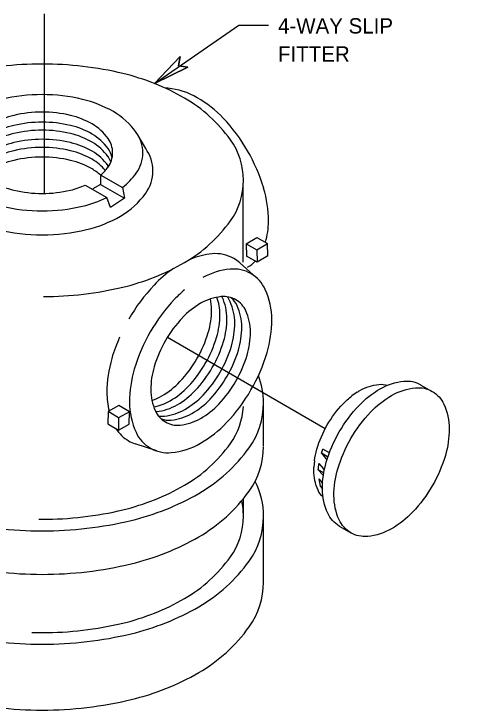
# Model space of a CAD drawing. Extents: x -224.9 to -217.6, y 224 to 234.
# Drawn here: x -223.209 to -221.41, y 227.932 to 230.657 of the extents above; entities that cross this region are included whole.
import ezdxf

# ---------------------------------------------------------------- set-up
doc = ezdxf.new("R2010")
doc.units = 0
for name, color, linetype in [('Default', 7, 'Continuous'), ('DETL-DIMS', 7, 'Continuous'), ('DETL-LINE', 7, 'Continuous'), ('DETL-NOTE', 7, 'Continuous')]:
    doc.layers.add(name, color=color, linetype=linetype)

# ---------------------------------------------------------------- blocks, each defined once
blk = doc.blocks.new('DWG009')
at = {"layer": 'Default'}
for p, q in [((-1.0426, -0.1786), (-1.0426, -0.0086)), ((1.0555, -0.1752), (1.0555, -0.0085)), ((-0.7214, -0.6491), (-0.7364, -0.6066)), ((-0.7214, -0.6151), (-0.7214, -0.6491)), ((-0.6471, -0.7137), (-0.7214, -0.6491)), ((-0.6471, -0.7137), (-0.6729, -0.6408)), ((-0.5779, -0.6986), (-0.5793, -0.6827)), ((-0.5502, -0.7768), (-0.5779, -0.6986)), ((-0.5502, -0.6939), (-0.5502, -0.7768)), ((-0.5037, -0.7299), (-0.5058, -0.7069)), ((-0.476, -0.8081), (-0.5037, -0.7299)), ((-0.375, -0.7689), (-0.3771, -0.7459)), ((-0.3473, -0.8471), (-0.375, -0.7689)), ((-0.3473, -0.7536), (-0.3473, -0.8471)), ((-0.2916, -0.7598), (-0.2916, -0.8591)), ((-0.476, -0.8763), (-0.5502, -0.8416)), ((0.5634, -0.8416), (0.4891, -0.8763))]:
    blk.add_line(p, q, dxfattribs=at)
for centre, radius, start, end in [((-0.1359, -0.6173), 1.1998, 103.44948, 120), ((0.0066, -1.2132), 1.8125, 90, 103.44948), ((0.0066, -1.2132), 1.8125, 76.55052, 90), ((0.1491, -0.6173), 1.1998, 60, 76.55052), ((-0.3528, -0.2417), 0.7661, 120, 144.34287), ((0.366, -0.2417), 0.7661, 35.65713, 60), ((-0.6801, -0.0069), 0.3633, 144.34287, 180), ((0.6932, -0.0069), 0.3633, 0, 35.65713), ((-0.6801, -0.0069), 0.3633, 180, 215.65713), ((0.6932, -0.0069), 0.3633, 324.34287, 360), ((-0.6801, -0.1783), 0.3633, 180, 215.65713), ((0.6932, -0.1783), 0.3633, 324.34287, 0), ((-0.3528, 0.2279), 0.7661, 215.65713, 240), ((0.366, 0.2279), 0.7661, 300, 324.34287), ((-0.3528, 0.0565), 0.7661, 215.65713, 240), ((-0.1359, 0.6035), 1.1998, 240, 256.55052), ((0.1491, 0.6035), 1.1998, 283.44948, 300), ((0.366, 0.0565), 0.7661, 300, 324.34287), ((-0.5427, -0.4784), 0.2906, 193.56979, 215.65713), ((-0.1359, 0.4321), 1.1998, 240, 256.55052), ((0.0066, 1.1995), 1.8125, 256.55052, 270), ((0.0066, 1.1995), 1.8125, 270, 283.44948), ((0.1491, 0.4321), 1.1998, 283.44948, 300), ((0.5559, -0.4784), 0.2906, 324.34287, 346.43021), ((-0.2809, -0.2905), 0.6128, 215.65713, 240), ((0.2941, -0.2905), 0.6128, 300, 324.34287), ((-0.115, 0.1519), 1.0256, 244.88835, 249.39036), ((0.0066, 1.028), 1.8125, 256.55052, 270), ((0.0066, 1.028), 1.8125, 270, 283.44948), ((-0.1074, 0.01), 0.9598, 240, 242.52731), ((-0.1074, 0.01), 0.9598, 247.41975, 256.55052), ((-0.1548, 0.0435), 0.9112, 257.80215, 261.45991), ((0.1206, 0.01), 0.9598, 283.44948, 292.58025), ((0.1206, 0.01), 0.9598, 297.47269, 300), ((0.0066, 0.4867), 1.45, 256.55052, 270), ((0.0066, 0.4867), 1.45, 270, 283.44948)]:
    blk.add_arc(centre, radius, start, end, dxfattribs=at)

msp = doc.modelspace()

# ---------------------------------------------------------------- linework, layer by layer
at = {"layer": 'DETL-DIMS'}
for p, q in [((-223.0898, 230.657), (-223.0898, 229.9543)), ((-222.6574, 230.3843), (-222.3274, 230.6133)), ((-222.3274, 230.6133), (-222.2118, 230.6133)), ((-222.6574, 230.3843), (-222.5575, 230.4897)), ((-222.5641, 230.4534), (-222.5575, 230.4897)), ((-222.6574, 230.3843), (-222.5274, 230.4491)), ((-222.5274, 230.4491), (-222.5641, 230.4534)), ((-222.6074, 229.3916), (-221.9886, 229.0343))]:
    msp.add_line(p, q, dxfattribs=at)
msp.add_lwpolyline([(-222.5274, 230.4491), (-222.6574, 230.3843), (-222.5575, 230.4897), (-222.5641, 230.4534)], close=True, dxfattribs=at)
at = {"layer": 'DETL-LINE'}
for p, q in [((-222.6924, 230.1301), (-222.7217, 230.1813)), ((-222.6924, 230.1301), (-222.6924, 230.1301)), ((-222.8688, 230.0256), (-222.8694, 229.9891)), ((-222.8679, 230.0264), (-222.7829, 229.9774)), ((-222.929, 229.9873), (-222.8449, 229.9388)), ((-222.8694, 229.9891), (-222.9, 229.9718)), ((-222.8694, 229.9891), (-222.7785, 229.9369)), ((-222.31, 229.6854), (-222.31, 229.9842)), ((-222.7829, 229.9774), (-222.7748, 229.9361)), ((-222.8305, 229.899), (-222.8449, 229.9388)), ((-222.7748, 229.9361), (-222.8305, 229.899)), ((-222.2982, 229.7578), (-222.2565, 229.7821)), ((-222.2565, 229.7821), (-222.2146, 229.7582)), ((-222.2982, 229.7578), (-222.2563, 229.7339)), ((-222.2982, 229.7578), (-222.298, 229.7095)), ((-222.2563, 229.7339), (-222.2146, 229.7582)), ((-222.2144, 229.7099), (-222.2146, 229.7582)), ((-222.256, 229.6856), (-222.298, 229.7095)), ((-222.2563, 229.7339), (-222.256, 229.6856)), ((-222.2144, 229.7099), (-222.256, 229.6856)), ((-222.2578, 229.6245), (-222.324, 229.6831)), ((-222.798, 229.1243), (-222.8399, 229.1004)), ((-222.7563, 229.1), (-222.798, 229.1243)), ((-222.2306, 228.9671), (-222.2306, 229.1343)), ((-222.8399, 229.1004), (-222.8402, 229.0521)), ((-222.7983, 229.076), (-222.8399, 229.1004)), ((-222.7563, 229.1), (-222.7983, 229.076)), ((-222.7566, 229.0517), (-222.7563, 229.1)), ((-222.7983, 229.076), (-222.7985, 229.0277)), ((-222.8402, 229.0521), (-222.7985, 229.0277)), ((-222.7985, 229.0277), (-222.7566, 229.0517)), ((-222.6493, 228.9464), (-222.7332, 228.9745)), ((-222.3094, 228.7012), (-222.3094, 228.759)), ((-222.2306, 228.4332), (-222.2306, 228.6907))]:
    msp.add_line(p, q, dxfattribs=at)
for centre, radius, start, end in [((-223.0979, 229.0997), 1.3612, 90, 103.4495), ((-223.0979, 229.0997), 1.3612, 76.5505, 90), ((-222.9909, 229.5473), 0.901, 60, 76.5505), ((-222.6192, 230.2305), 0.1364, 84.3429, 88.9523), ((-222.6341, 230.08), 0.2877, 60, 84.3429), ((-223.0979, 229.6606), 0.6806, 90, 103.4495), ((-223.0979, 229.6606), 0.6806, 76.5505, 90), ((-223.0444, 229.8843), 0.4505, 60, 76.5505), ((-222.828, 229.8293), 0.5753, 35.6571, 60), ((-222.7155, 229.939), 0.4505, 43.4495, 60), ((-223.1354, 229.9531), 0.3154, 103.4495, 111.2855), ((-223.0979, 229.7964), 0.4764, 90, 103.4495), ((-223.0979, 229.7964), 0.4764, 76.5505, 90), ((-223.0604, 229.9531), 0.3154, 60, 76.5505), ((-222.963, 230.0254), 0.2877, 35.6571, 60), ((-223.0979, 229.7571), 0.4764, 90, 103.4495), ((-223.0979, 229.7571), 0.4764, 76.5505, 90), ((-222.8825, 229.7807), 0.6806, 30, 43.4495), ((-223.1354, 229.9138), 0.3154, 103.4495, 120), ((-223.0979, 229.7256), 0.4764, 90, 103.4495), ((-223.0979, 229.7256), 0.4764, 76.5505, 90), ((-223.0604, 229.9138), 0.3154, 60, 76.5505), ((-223.0034, 230.0518), 0.2014, 35.6571, 60), ((-223.1354, 229.8822), 0.3154, 103.4495, 120), ((-223.0604, 229.8822), 0.3154, 60, 76.5505), ((-223.0034, 230.0125), 0.2014, 35.6571, 60), ((-222.8401, 230.1135), 0.1364, 0, 35.6571), ((-223.1354, 229.8465), 0.3154, 103.4495, 120), ((-223.0979, 229.6899), 0.4764, 90, 103.4495), ((-223.0979, 229.6899), 0.4764, 76.5505, 90), ((-223.0604, 229.8465), 0.3154, 60, 76.5505), ((-223.0034, 229.9809), 0.2014, 35.6571, 60), ((-222.9174, 230.1135), 0.0955, 360, 35.6571), ((-222.5822, 230.0057), 0.2728, 0, 35.6571), ((-223.1354, 229.8149), 0.3154, 103.4495, 120), ((-223.0979, 229.6583), 0.4764, 90, 103.4495), ((-223.0979, 229.6583), 0.4764, 76.5505, 90), ((-223.0604, 229.8149), 0.3154, 60, 76.5505), ((-223.0034, 229.9452), 0.2014, 35.6571, 60), ((-222.9174, 230.0742), 0.0955, 11.8812, 35.6571), ((-222.8143, 230.0427), 0.15, 0, 35.6571), ((-222.8825, 229.7807), 0.6806, 16.5505, 30), ((-223.0979, 229.6205), 0.4764, 90, 103.4495), ((-223.0979, 229.6205), 0.4764, 76.5505, 90), ((-222.9174, 230.1135), 0.0955, 324.3429, 0), ((-222.9174, 230.0427), 0.0955, 21.7855, 35.6571), ((-222.8401, 230.1135), 0.1364, 324.3429, 0), ((-223.1354, 229.7772), 0.3154, 103.4495, 120), ((-223.0604, 229.7772), 0.3154, 60, 76.5505), ((-223.0034, 229.9137), 0.2014, 40.5066, 60), ((-223.0034, 229.8759), 0.2014, 48.0169, 60), ((-223.0034, 230.1753), 0.2014, 312.3296, 324.3429), ((-222.9174, 230.007), 0.0955, 33.9269, 35.6571), ((-222.8143, 230.0427), 0.15, 324.3429, 360), ((-222.963, 230.2017), 0.2877, 308.7475, 324.3429), ((-223.1354, 230.274), 0.3154, 240, 256.5505), ((-223.0604, 230.274), 0.3154, 283.4495, 294.6403), ((-222.5822, 230.0057), 0.2728, 324.3429, 360), ((-223.0979, 230.4306), 0.4764, 256.5505, 270), ((-223.0979, 230.4306), 0.4764, 270, 283.4495), ((-222.9495, 230.1396), 0.3164, 300, 324.3429), ((-222.662, 229.8463), 0.4505, 0, 16.5505), ((-223.0444, 230.3427), 0.4505, 283.4495, 296.2827), ((-223.0979, 230.5665), 0.6806, 256.5505, 270), ((-223.0979, 230.5665), 0.6806, 270, 283.4495), ((-223.039, 230.2948), 0.4956, 283.4495, 300), ((-222.828, 230.182), 0.5753, 300, 324.3429), ((-222.4991, 229.8463), 0.2877, 343.2518, 360), ((-223.0979, 230.5409), 0.7487, 256.5505, 270), ((-223.0979, 230.5409), 0.7487, 270, 283.4495), ((-222.4029, 229.419), 0.3006, 95.6571, 112.0676), ((-222.4185, 229.5763), 0.1425, 60, 95.6571), ((-222.9909, 230.4641), 0.901, 283.4495, 300), ((-222.4185, 229.5763), 0.1425, 48.5074, 60), ((-222.3613, 229.7839), 0.1364, 300.1223, 316.1787), ((-222.3178, 229.2717), 0.4708, 124.3561, 136.5505), ((-222.3333, 229.3718), 0.2877, 95.6571, 118.0014), ((-222.3482, 229.5223), 0.1364, 60, 95.6571), ((-222.3482, 229.5223), 0.1364, 24.3429, 60), ((-223.0979, 230.9117), 1.3612, 270.2128, 283.4495), ((-222.1433, 229.1063), 0.7112, 136.5505, 149.9079), ((-222.2519, 229.2308), 0.4505, 129.7851, 136.5505), ((-222.486, 229.46), 0.2877, 360, 24.3429), ((-222.3764, 229.35), 0.2014, 95.6571, 120), ((-222.603, 229.4808), 0.2014, 0, 19.4934), ((-222.3869, 229.4554), 0.0955, 60, 95.6571), ((-222.4792, 229.5086), 0.0955, 24.3429, 26.0731), ((-222.5756, 229.465), 0.2014, 0, 24.3429), ((-222.4482, 229.4908), 0.0955, 24.3429, 38.2145), ((-222.4209, 229.475), 0.0955, 24.3429, 48.1188), ((-222.0848, 229.0726), 0.6806, 136.5505, 150), ((-222.3194, 229.2513), 0.3154, 120, 136.5505), ((-222.6357, 229.4997), 0.2014, 360, 11.9831), ((-222.5447, 229.4471), 0.2014, 0, 24.3429), ((-222.3869, 229.4554), 0.0955, 24.3429, 60), ((-222.7497, 229.4997), 0.3154, 343.4495, 0), ((-222.5174, 229.4314), 0.2014, 360, 24.3429), ((-222.4833, 229.4117), 0.2014, 0, 24.3429), ((-222.2025, 229.1405), 0.4764, 136.5505, 150), ((-222.717, 229.4808), 0.3154, 343.4495, 0), ((-222.6896, 229.465), 0.3154, 343.4495, 0), ((-222.6587, 229.4471), 0.3154, 343.4495, 0), ((-222.6488, 229.46), 0.4505, 343.4495, 360), ((-222.0848, 229.0726), 0.6806, 150, 163.4495), ((-222.9041, 229.5456), 0.4764, 330, 343.4495), ((-222.6314, 229.4314), 0.3154, 343.4495, 0), ((-222.5973, 229.4117), 0.3154, 343.4495, 0), ((-222.1433, 229.1063), 0.7112, 156.3092, 163.4495), ((-222.8714, 229.5267), 0.4764, 330, 343.4495), ((-222.2025, 229.1405), 0.4764, 150, 163.4495), ((-222.844, 229.5109), 0.4764, 330, 343.4495), ((-222.8131, 229.493), 0.4764, 330, 343.4495), ((-222.7858, 229.4773), 0.4764, 330, 343.4495), ((-222.8694, 229.5255), 0.6806, 330, 343.4495), ((-222.3737, 229.1748), 0.4708, 163.4495, 180), ((-222.9041, 229.5456), 0.4764, 316.5505, 330), ((-222.7517, 229.4576), 0.4764, 330, 343.4495), ((-222.3569, 229.1864), 0.3154, 163.4495, 180), ((-222.8714, 229.5267), 0.4764, 316.5505, 330), ((-222.3054, 229.1381), 0.4505, 163.4495, 180), ((-222.844, 229.5109), 0.4764, 316.5505, 330), ((-222.8131, 229.493), 0.4764, 316.5505, 330), ((-222.7858, 229.4773), 0.4764, 316.5505, 330), ((-222.7517, 229.4576), 0.4764, 316.5505, 330), ((-222.5307, 229.1343), 0.3001, 0, 21.063), ((-222.7871, 229.4348), 0.3154, 300, 316.5505), ((-222.7544, 229.4159), 0.3154, 300, 316.5505), ((-222.5439, 229.1748), 0.3006, 180, 193.863), ((-222.4709, 229.1864), 0.2014, 180, 204.3429), ((-222.7271, 229.4001), 0.3154, 300, 316.5505), ((-222.6962, 229.3823), 0.3154, 300, 316.5505), ((-222.8694, 229.5255), 0.6806, 316.5505, 330), ((-222.4682, 229.1381), 0.2877, 180, 204.3429), ((-222.7301, 229.3361), 0.2014, 288.0169, 300), ((-222.6974, 229.3172), 0.2014, 280.5066, 300), ((-222.6688, 229.3665), 0.3154, 300, 316.5505), ((-222.6701, 229.3014), 0.2014, 275.6571, 300), ((-222.6348, 229.3468), 0.3154, 300, 316.5505), ((-222.5822, 229.1343), 0.2728, 324.3429, 356.9926), ((-222.5307, 229.1343), 0.3001, 324.3429, 0), ((-222.5674, 229.1427), 0.0955, 204.3429, 240), ((-222.6597, 229.196), 0.0955, 273.9269, 275.6571), ((-222.6287, 229.1782), 0.0955, 261.7855, 275.6571), ((-222.6392, 229.2835), 0.2014, 275.6571, 300), ((-222.6118, 229.2678), 0.2014, 275.6571, 300), ((-222.6014, 229.1624), 0.0955, 251.8812, 275.6571), ((-222.5674, 229.1427), 0.0955, 240, 275.6571), ((-222.5778, 229.2481), 0.2014, 275.6571, 300), ((-222.7024, 229.3673), 0.4505, 300, 316.5505), ((-222.6879, 229.1096), 0.1425, 212.2516, 240), ((-222.606, 229.0758), 0.1364, 204.3429, 240), ((-222.6879, 229.1096), 0.1425, 240, 251.4926), ((-222.6209, 229.2263), 0.2877, 275.6571, 300), ((-222.828, 229.3106), 0.5753, 300, 324.3429), ((-222.606, 229.0758), 0.1364, 240, 275.6571), ((-222.801, 229.3282), 0.6328, 300, 324.3429), ((-222.5307, 228.9643), 0.3001, 324.3429, 0), ((-222.9909, 229.5927), 0.901, 283.4495, 300), ((-222.5307, 228.6907), 0.3001, 360, 27.1212), ((-222.801, 229.1583), 0.6328, 300, 324.3429), ((-222.9802, 229.6385), 0.9911, 283.4495, 300), ((-222.5822, 228.6907), 0.2728, 0, 12.8696), ((-223.0979, 230.0402), 1.3612, 270, 283.4495), ((-223.0979, 230.1308), 1.4973, 256.5505, 270), ((-223.0979, 230.0402), 1.3612, 269.4429, 270), ((-223.0979, 230.1308), 1.4973, 270, 283.4495), ((-222.5822, 228.6907), 0.2728, 324.3429, 360), ((-222.5307, 228.6907), 0.3001, 324.3429, 0), ((-222.9802, 229.4686), 0.9911, 283.4495, 300), ((-222.828, 228.867), 0.5753, 300, 324.3429), ((-222.801, 228.8847), 0.6328, 300, 324.3429), ((-223.0979, 229.9609), 1.4973, 256.5505, 270), ((-223.0979, 229.9609), 1.4973, 270, 283.4495), ((-222.5307, 228.4332), 0.3001, 324.3429, 0), ((-222.9909, 229.1491), 0.901, 283.4495, 300), ((-222.9802, 229.1949), 0.9911, 283.4495, 300), ((-223.0979, 229.5967), 1.3612, 270, 283.4495), ((-222.801, 228.6271), 0.6328, 300, 324.3429), ((-223.0979, 229.6873), 1.4973, 256.5505, 270), ((-223.0979, 229.5967), 1.3612, 268.2962, 270), ((-223.0979, 229.6873), 1.4973, 270, 283.4495), ((-222.9802, 228.9374), 0.9911, 283.4495, 300), ((-223.0979, 229.4297), 1.4973, 256.5505, 270), ((-223.0979, 229.4297), 1.4973, 270, 283.4495)]:
    msp.add_arc(centre, radius, start, end, dxfattribs=at)

# ---------------------------------------------------------------- block references
at = {"layer": 'DETL-LINE', "xscale": 0.3041567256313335, "yscale": -0.30415672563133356, "rotation": 60.00000000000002}
msp.add_blockref('DWG009', (-221.7282, 228.9), dxfattribs=at)

# ---------------------------------------------------------------- texts
at = {"layer": 'DETL-NOTE'}
for s, p in [('4-WAY SLIP ', (-222.1738, 230.5803)), ('FITTER', (-222.1738, 230.4703))]:
    msp.add_text(s, height=0.06, dxfattribs=at).set_placement(p)

doc.saveas('drawing.dxf')
